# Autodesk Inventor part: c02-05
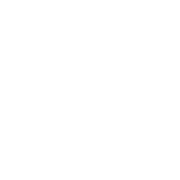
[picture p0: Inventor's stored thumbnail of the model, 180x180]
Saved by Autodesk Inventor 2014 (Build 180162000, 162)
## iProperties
Created: 2013-02
Part Number: c02-05
Material: Aluminum 2014-T6
Document SubType Name: Modeling
Designer: Thom Tremblay
Density: 2.78927 g/cm^3
Appearance: Satin
Author: Thom Tremblay
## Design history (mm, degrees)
sketch "Sketch1"
  geometry: L1 (100, 60)-(-100, 60); L2 (-100, 60)-(-100, -60); L3 (-100, -60)-(100, -60); L4 (100, -60)-(100, 60); L5 (100, 60)-(-100, -60); L6 (-100, 60)-(100, -60); 1 further point
  constraints: 12 end point, 2 midpoint, 2 parallel, 1 horizontal, 1 perpendicular
  dimensions: "d0" = 200 distance of L3.end L2.end; "d1" = 120 distance of L2.end L1.end
extrude "Extrusion1" new body sketch "Sketch1" stored distance "d2" = 80; taper "d3" = 0 deg
sketch "Sketch2"
  geometry: L1 (100, 60)-(-100, 60) reference; L2 (100, -60)-(25, -60); L3 (25, -60)-(25, 60); L4 (25, 60)-(100, 60); L5 (100, 60)-(100, -60); 1 further point
  constraints: 8 end point, 2 parallel, 1 horizontal, 1 perpendicular, 1 point on line
  dimensions: "d4" = 75 distance of L3.end L4.end
extrude "Extrusion2" join sketch "Sketch2" distance "d5" = 90; taper "d6" = 0 deg
chamfer "Chamfer1" distance "d7" = 30; stored, may be unused: second distance "d8" = 80, angle "d9" = 45 deg
body "Solid1"
